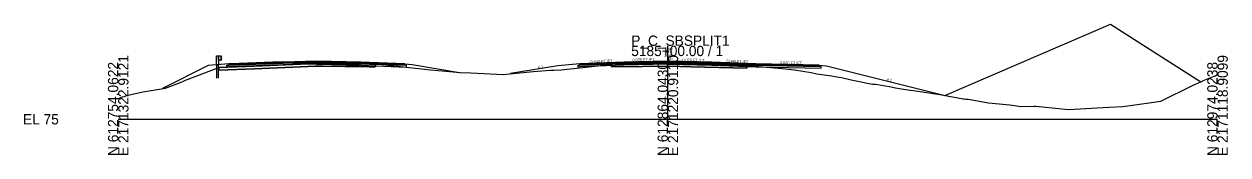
# Model space of a CAD drawing. Extents: x -26 to 1303, y -3010 to 12033.
# Drawn here: x -25.7 to 302.8, y 6990.3 to 7025.9 of the extents above; entities that cross this region are included whole.
import ezdxf

# ---------------------------------------------------------------- set-up
doc = ezdxf.new("R2010")
doc.units = 0
for name, color, linetype in [('RD_GPK_XS_Cell', 7, 'Continuous'), ('RD_PD_Final_TrvlWay', 7, 'Continuous'), ('RD_Sketch10', 7, 'Continuous'), ('RD_XS_Base', 7, 'Continuous'), ('RD_XS_ExGround', 7, 'Continuous'), ('RD_XS_ExPaveRet', 7, 'Continuous'), ('RD_XS_GR', 7, 'Continuous'), ('RD_XS_Greenside', 7, 'Continuous'), ('RD_XS_Pave', 7, 'Continuous'), ('RD_XS_PaveOvlay_CP', 7, 'Continuous'), ('RD_XS_TieSlope', 7, 'Continuous'), ('RD_XS_TX_Elev_EX', 7, 'Continuous'), ('RD_XS_TX_Elev_PR', 7, 'Continuous'), ('RD_XS_TX_Slope', 7, 'Continuous')]:
    doc.layers.add(name, color=color, linetype=linetype)

msp = doc.modelspace()

# ---------------------------------------------------------------- linework, layer by layer
at = {"layer": 'RD_GPK_XS_Cell'}
for p, q in [((150, 7000), (150, 7020)), ((0, 7000), (150, 7000)), ((150, 7000), (300, 7000))]:
    msp.add_line(p, q, dxfattribs=at)
at = {"layer": 'RD_PD_Final_TrvlWay'}
msp.add_lwpolyline([(27.34, 7011.23), (27.34, 7014.83), (26.84, 7014.79), (26.84, 7011.23)], dxfattribs=at)
at = {"layer": 'RD_Sketch10'}
msp.add_lwpolyline([(225.61, 7006.48), (270.8, 7025.9), (295.43, 7010.2)], dxfattribs=at)
at = {"layer": 'RD_XS_Base'}
for p, q in [((29.68, 7014.34), (29.68, 7014.72)), ((29.68, 7014.72), (29.79, 7014.72)), ((29.68, 7014.22), (29.68, 7014.34)), ((29.79, 7014.22), (29.68, 7014.22)), ((29.79, 7014.72), (30.18, 7014.74)), ((30.18, 7014.24), (29.79, 7014.22)), ((30.18, 7014.74), (32.99, 7014.85)), ((32.99, 7014.35), (30.18, 7014.24)), ((32.99, 7014.85), (42.18, 7015.22)), ((42.18, 7014.72), (32.99, 7014.35)), ((42.18, 7015.22), (45.02, 7015.28)), ((45.02, 7014.78), (42.18, 7014.72)), ((45.02, 7015.28), (54.18, 7015.46)), ((54.18, 7014.96), (45.02, 7014.78)), ((54.18, 7015.5), (54.18, 7015.62)), ((54.18, 7015.62), (54.18, 7015.12)), ((54.18, 7015.46), (54.18, 7015.62)), ((54.18, 7015.62), (54.18, 7014.96)), ((54.18, 7015.46), (54.18, 7015.5)), ((54.18, 7015.46), (54.18, 7015.08)), ((54.18, 7015.46), (54.18, 7014.96)), ((66.18, 7015.22), (54.18, 7015.46)), ((54.18, 7015.46), (54.18, 7015.46)), ((54.18, 7015.12), (54.18, 7014.96)), ((54.18, 7015.08), (54.18, 7014.96)), ((54.18, 7014.96), (54.18, 7014.96)), ((54.18, 7014.96), (54.18, 7014.96)), ((54.18, 7014.96), (66.18, 7014.72)), ((78.18, 7014.74), (66.18, 7015.22)), ((66.18, 7014.72), (78.68, 7014.22)), ((68.18, 7015.14), (68.18, 7015.14)), ((68.18, 7014.64), (68.18, 7014.64)), ((78.68, 7014.72), (78.18, 7014.74)), ((78.18, 7014.74), (78.18, 7014.74)), ((78.68, 7014.22), (78.68, 7014.72)), ((78.68, 7014.72), (78.68, 7014.72)), ((78.68, 7014.22), (78.68, 7014.22)), ((78.68, 7014.22), (78.68, 7014.22)), ((125.5, 7014.72), (126, 7014.74)), ((125.5, 7014.22), (125.5, 7014.72)), ((125.5, 7014.72), (125.5, 7014.72)), ((126, 7014.24), (125.5, 7014.22)), ((125.5, 7014.22), (125.5, 7014.22)), ((125.5, 7014.22), (125.5, 7014.22)), ((126, 7014.74), (138, 7015.22)), ((126, 7014.74), (126, 7014.74)), ((138, 7014.72), (126, 7014.24)), ((126, 7014.24), (126, 7014.24)), ((136, 7015.14), (136, 7015.14)), ((136, 7014.64), (136, 7014.64)), ((138, 7015.22), (150, 7015.46)), ((150, 7014.96), (138, 7014.72)), ((150, 7015.46), (150, 7015.62)), ((150, 7015.62), (150, 7014.96)), ((150, 7015.46), (150, 7015.46)), ((162, 7015.22), (150, 7015.46)), ((150, 7015.46), (150, 7015.46)), ((150, 7015.46), (150, 7014.96)), ((150, 7014.96), (150, 7014.96)), ((150, 7014.96), (162, 7014.72)), ((150, 7014.96), (150, 7014.96)), ((174, 7014.74), (162, 7015.22)), ((162, 7015.22), (162, 7015.22)), ((162, 7014.72), (162, 7014.72)), ((162, 7014.72), (174, 7014.24)), ((191.3, 7014.4), (174, 7014.74)), ((174, 7014.74), (174, 7014.74)), ((174, 7014.24), (174, 7014.24)), ((174, 7014.24), (191.8, 7013.89)), ((191.8, 7014.39), (191.3, 7014.4)), ((191.3, 7014.4), (191.3, 7014.4)), ((191.8, 7013.89), (191.8, 7014.39)), ((191.8, 7014.39), (191.8, 7014.39)), ((191.8, 7013.89), (191.8, 7013.89)), ((191.8, 7013.89), (191.8, 7013.89))]:
    msp.add_line(p, q, dxfattribs=at)
at = {"layer": 'RD_XS_ExGround'}
msp.add_lwpolyline([(0, 7005.65), (1.18, 7006.09), (1.69, 7006.23), (2.29, 7006.43), (6.68, 7007.48), (9.01, 7007.81), (12.9, 7008.46), (17.18, 7010.12), (17.59, 7010.3), (18.38, 7010.62), (27.44, 7014.09), (49.76, 7015), (54.51, 7015.21), (61.92, 7015.12), (66.65, 7015.07), (70.14, 7015.01), (71.99, 7014.89), (76.11, 7014.42), (85.24, 7013.5), (89.39, 7013.05), (93.31, 7012.7), (96.2, 7012.6), (105.08, 7012.23), (113.24, 7013), (117.98, 7013.41), (118.85, 7013.41), (120.89, 7013.49), (128.46, 7014.31), (130.87, 7014.59), (134.63, 7014.98), (143.07, 7015.09), (150.3, 7015.18), (156.31, 7015.02), (171.55, 7014.62), (181.17, 7013.78), (184.57, 7013.5), (189.08, 7012.72), (190.64, 7012.39), (194.65, 7011.82), (196.66, 7011.5), (197.35, 7011.36), (200.03, 7010.78), (205.8, 7009.56), (206.75, 7009.54), (210.91, 7008.86), (212.16, 7008.53), (212.69, 7008.5), (214.26, 7008.21), (219.45, 7007.5), (224.75, 7006.62), (230.62, 7005.6), (230.88, 7005.58), (231.35, 7005.5), (231.94, 7005.43), (237.46, 7004.5), (243.33, 7003.91), (246.46, 7003.5), (249.99, 7003.55), (250.4, 7003.55), (252.26, 7003.37), (259.31, 7002.66), (270.35, 7003.27), (274.03, 7003.5), (275.56, 7003.67), (284.54, 7004.93), (293.32, 7009.24), (295.43, 7010.2), (296.33, 7010.66), (300, 7012.09)], dxfattribs=at)
at = {"layer": 'RD_XS_ExPaveRet'}
for points in [[(69.46, 7015.02), (70.14, 7015.01), (70.14, 7014.64), (70.14, 7014.26), (69.46, 7014.27), (68.53, 7014.28), (65.72, 7014.33), (61.92, 7014.37), (55.73, 7014.44), (54.51, 7014.46), (53.73, 7014.42), (49.76, 7014.25), (37.22, 7013.74), (27.44, 7013.34), (27.44, 7013.34), (27.44, 7013.73), (27.44, 7014.09), (27.44, 7014.09), (37.22, 7014.49), (49.76, 7015), (53.73, 7015.17), (54.51, 7015.21), (55.73, 7015.19), (61.92, 7015.12), (65.72, 7015.08), (68.53, 7015.03), (69.46, 7015.02)], [(68.53, 7015.03), (65.72, 7015.08), (61.92, 7015.12), (55.73, 7015.19), (54.51, 7015.21), (53.73, 7015.17), (49.76, 7015), (37.22, 7014.49), (27.44, 7014.09), (27.44, 7013.73), (27.44, 7013.34), (37.22, 7013.74), (49.76, 7014.25), (53.73, 7014.42), (54.51, 7014.46), (55.73, 7014.44), (61.92, 7014.37), (65.72, 7014.33), (68.53, 7014.28), (69.46, 7014.27), (70.14, 7014.26), (70.14, 7014.64), (70.14, 7015.01), (69.46, 7015.02), (68.53, 7015.03)], [(171.55, 7014.62), (171.55, 7014.62), (171.55, 7013.87), (156.31, 7014.27), (156.31, 7014.27), (150.3, 7014.43), (150.3, 7014.43), (150.3, 7014.43), (143.07, 7014.34), (143.07, 7014.34), (134.63, 7014.23), (134.63, 7014.23), (134.63, 7014.98), (143.07, 7015.09), (143.07, 7015.09), (150.3, 7015.18), (150.3, 7015.18), (150.3, 7015.18), (156.31, 7015.02), (156.31, 7015.02), (171.55, 7014.62)], [(156.31, 7015.02), (150.3, 7015.18), (143.07, 7015.09), (134.63, 7014.98), (134.63, 7014.23), (143.07, 7014.34), (150.3, 7014.43), (156.31, 7014.27), (171.55, 7013.87), (171.55, 7014.62), (156.31, 7015.02)]]:
    msp.add_lwpolyline(points, dxfattribs=at)
at = {"layer": 'RD_XS_GR'}
for p, q in [((26.84, 7014.79), (26.84, 7017.23)), ((26.84, 7017.23), (27.09, 7017.23)), ((27.34, 7014.83), (26.84, 7014.79)), ((27.09, 7017.23), (27.34, 7017.23)), ((27.34, 7017.23), (27.34, 7014.83)), ((27.34, 7016.06), (27.34, 7017.23)), ((27.34, 7017.23), (28.01, 7017.23)), ((28.01, 7016.06), (27.34, 7016.06)), ((28.01, 7017.23), (28.01, 7016.06)), ((28.22, 7017), (28.01, 7017.23)), ((28.01, 7017.23), (28.01, 7016.33)), ((28.01, 7016.64), (28.07, 7016.71)), ((28.22, 7016.42), (28.01, 7016.64)), ((28.01, 7016.33), (28.01, 7016.06)), ((28.01, 7016.06), (28.07, 7016.13)), ((28.07, 7016.71), (28.28, 7016.93)), ((28.07, 7016.13), (28.28, 7016.35)), ((28.28, 7016.93), (28.22, 7017)), ((28.28, 7016.35), (28.22, 7016.42))]:
    msp.add_line(p, q, dxfattribs=at)
at = {"layer": 'RD_XS_Greenside'}
for p, q in [((24.53, 7014.61), (12.08, 7008.38)), ((80.18, 7014.9), (93.1, 7012.74)), ((120, 7014.58), (107.01, 7012.42)), ((193.3, 7014.55), (225.69, 7006.46))]:
    msp.add_line(p, q, dxfattribs=at)
at = {"layer": 'RD_XS_Pave'}
for p, q in [((32.99, 7015.17), (30.18, 7015.06)), ((30.18, 7015.06), (30.18, 7014.94)), ((32.99, 7015.01), (30.18, 7014.9)), ((30.18, 7014.9), (32.99, 7015.01)), ((30.18, 7014.94), (30.18, 7014.9)), ((30.18, 7014.9), (30.18, 7014.78)), ((30.18, 7014.74), (32.99, 7014.85)), ((30.18, 7014.78), (30.18, 7014.74)), ((42.18, 7015.54), (32.99, 7015.17)), ((42.18, 7015.38), (32.99, 7015.01)), ((32.99, 7015.01), (42.18, 7015.38)), ((32.99, 7014.85), (42.18, 7015.22)), ((45.02, 7015.59), (42.18, 7015.54)), ((45.02, 7015.43), (42.18, 7015.38)), ((42.18, 7015.38), (45.02, 7015.43)), ((42.18, 7015.22), (45.02, 7015.28)), ((54.18, 7015.78), (45.02, 7015.59)), ((54.18, 7015.62), (45.02, 7015.43)), ((45.02, 7015.43), (54.18, 7015.62)), ((45.02, 7015.28), (54.18, 7015.46)), ((66.18, 7015.54), (54.18, 7015.78)), ((54.18, 7015.5), (54.18, 7015.62)), ((54.18, 7015.62), (54.18, 7015.5)), ((54.18, 7015.46), (54.18, 7015.62)), ((54.18, 7015.62), (66.18, 7015.38)), ((66.18, 7015.38), (54.18, 7015.62)), ((54.18, 7015.62), (54.18, 7015.46)), ((54.18, 7015.46), (54.18, 7015.5)), ((54.18, 7015.5), (54.18, 7015.46)), ((54.18, 7015.46), (54.18, 7015.46)), ((54.18, 7015.46), (54.18, 7015.46)), ((54.18, 7015.46), (66.18, 7015.22)), ((78.18, 7015.06), (66.18, 7015.54)), ((66.18, 7015.38), (78.18, 7014.9)), ((78.18, 7014.9), (66.18, 7015.38)), ((66.18, 7015.22), (78.18, 7014.74)), ((68.18, 7015.46), (68.18, 7015.46)), ((68.18, 7015.3), (68.18, 7015.3)), ((68.18, 7015.3), (68.18, 7015.3)), ((68.18, 7015.14), (68.18, 7015.14)), ((78.18, 7014.9), (78.18, 7015.06)), ((78.18, 7015.06), (78.18, 7015.06)), ((78.18, 7014.9), (78.18, 7014.9)), ((78.18, 7014.9), (78.18, 7014.9)), ((78.18, 7014.74), (78.18, 7014.9)), ((78.18, 7014.9), (78.18, 7014.9)), ((78.18, 7014.74), (78.18, 7014.74)), ((78.18, 7014.74), (78.18, 7014.74)), ((138, 7015.54), (126, 7015.06)), ((138, 7015.38), (126, 7014.9)), ((126, 7014.9), (138, 7015.38)), ((126, 7014.74), (138, 7015.22)), ((126, 7015.06), (126, 7015.06)), ((126, 7015.06), (126, 7014.9)), ((126, 7014.9), (126, 7014.9)), ((126, 7014.9), (126, 7014.74)), ((126, 7014.9), (126, 7014.9)), ((126, 7014.9), (126, 7014.9)), ((126, 7014.74), (126, 7014.74)), ((126, 7014.74), (126, 7014.74)), ((136, 7015.46), (136, 7015.46)), ((136, 7015.3), (136, 7015.3)), ((136, 7015.3), (136, 7015.3)), ((136, 7015.14), (136, 7015.14)), ((150, 7015.78), (138, 7015.54)), ((150, 7015.62), (138, 7015.38)), ((138, 7015.38), (150, 7015.62)), ((138, 7015.22), (150, 7015.46)), ((162, 7015.54), (150, 7015.78)), ((150, 7015.46), (150, 7015.62)), ((150, 7015.62), (162, 7015.38)), ((162, 7015.38), (150, 7015.62)), ((150, 7015.62), (150, 7015.62)), ((150, 7015.62), (150, 7015.46)), ((150, 7015.46), (150, 7015.46)), ((150, 7015.46), (150, 7015.46)), ((150, 7015.46), (150, 7015.46)), ((150, 7015.46), (162, 7015.22)), ((174, 7015.06), (162, 7015.54)), ((162, 7015.54), (162, 7015.54)), ((162, 7015.38), (162, 7015.38)), ((162, 7015.38), (174, 7014.9)), ((174, 7014.9), (162, 7015.38)), ((162, 7015.38), (162, 7015.38)), ((162, 7015.22), (162, 7015.22)), ((162, 7015.22), (174, 7014.74)), ((191.3, 7014.71), (174, 7015.06)), ((174, 7015.06), (174, 7015.06)), ((174, 7014.9), (174, 7014.9)), ((174, 7014.9), (191.3, 7014.56)), ((191.3, 7014.56), (174, 7014.9)), ((174, 7014.9), (174, 7014.9)), ((174, 7014.74), (174, 7014.74)), ((174, 7014.74), (191.3, 7014.4)), ((191.3, 7014.56), (191.3, 7014.71)), ((191.3, 7014.71), (191.3, 7014.71)), ((191.3, 7014.56), (191.3, 7014.56)), ((191.3, 7014.56), (191.3, 7014.56)), ((191.3, 7014.4), (191.3, 7014.56)), ((191.3, 7014.56), (191.3, 7014.56)), ((191.3, 7014.4), (191.3, 7014.4)), ((191.3, 7014.4), (191.3, 7014.4))]:
    msp.add_line(p, q, dxfattribs=at)
at = {"layer": 'RD_XS_PaveOvlay_CP'}
for p, q in [((30.18, 7015.06), (42.18, 7015.54)), ((42.18, 7015.54), (54.18, 7015.78)), ((54.18, 7015.78), (66.18, 7015.54)), ((66.18, 7015.54), (78.18, 7015.06)), ((138, 7015.54), (126, 7015.06)), ((126, 7015.06), (126, 7015.06)), ((136, 7015.46), (136, 7015.46)), ((150, 7015.78), (138, 7015.54)), ((162, 7015.54), (150, 7015.78)), ((174, 7015.06), (162, 7015.54)), ((162, 7015.54), (162, 7015.54)), ((191.3, 7014.71), (174, 7015.06)), ((174, 7015.06), (174, 7015.06)), ((191.3, 7014.71), (191.3, 7014.71))]:
    msp.add_line(p, q, dxfattribs=at)
at = {"layer": 'RD_XS_TieSlope'}
for p, q in [((30.18, 7015.06), (24.53, 7014.61)), ((78.18, 7015.06), (80.18, 7014.9)), ((126, 7015.06), (120, 7014.58)), ((191.3, 7014.71), (193.3, 7014.55))]:
    msp.add_line(p, q, dxfattribs=at)

# ---------------------------------------------------------------- texts
at = {"layer": 'RD_GPK_XS_Cell'}
for s, p in [('P_C_SBSPLIT1', (140, 7020)), ('5185+00.00 / 1', (140, 7017.2)), ('EL 75', (-26, 6998.6))]:
    msp.add_text(s, height=2.8, dxfattribs=at).set_placement(p)
for s, p in [('N 612754.0622', (0, 6990)), ('E 2171322.9121', (2.8, 6990)), ('N 612864.0430', (150, 6990)), ('E 2171220.9110', (152.8, 6990)), ('N 612974.0238', (300, 6990)), ('E 2171118.9099', (302.8, 6990))]:
    msp.add_text(s, height=2.8, rotation=90, dxfattribs=at).set_placement(p)
at = {"layer": 'RD_XS_TX_Elev_EX'}
msp.add_text('90.18', height=0.6, rotation=90, dxfattribs=at).set_placement((149.72, 7016.9))
at = {"layer": 'RD_XS_TX_Elev_PR'}
msp.add_text('90.78', height=1, rotation=90, dxfattribs=at).set_placement((151.22, 7016.08))
at = {"layer": 'RD_XS_TX_Slope'}
for s, rotation, p in [('6:1', 9.4623, (114.67, 7013.75)), ('0.040 FT./FT.', 2.2906, (128.93, 7015.28)), ('0.020 FT./FT.', 1.1458, (140.34, 7015.77)), ('0.020 FT./FT.', 358.8542, (153.94, 7015.8)), ('0.040 FT./FT.', 357.7094, (165.94, 7015.48)), ('0.020 FT./FT.', 358.8542, (180.59, 7015.03)), ('4:1', 345.9638, (209.67, 7010.52))]:
    msp.add_text(s, height=0.75, rotation=rotation, dxfattribs=at).set_placement(p)

doc.saveas('drawing.dxf')
